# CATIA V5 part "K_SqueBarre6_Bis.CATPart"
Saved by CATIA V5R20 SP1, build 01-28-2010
Part number: squelette_barre_6_bis
Publications: "Point.1", "Point.2", "Droite.1", "Point.3", "Plan.1", "Droite.2", "Droite.3", "Droite.4", "Point.4"
Bounding box of the stored display mesh (mm): x 0 to 0, y -2 to 20, z 0 to 45
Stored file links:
  G:\Khaled_CFAO_2011\ST2M\ST2M_GR2\gcausse\Khaled\CAD_ThinkMotion\K_SqueBarre6_Bis.CATPart
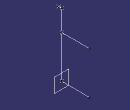
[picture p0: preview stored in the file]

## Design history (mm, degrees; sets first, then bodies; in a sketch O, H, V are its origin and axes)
Set1
  Point1: (0, 0, 0)
  Point2: (0, 0, 30)
  Line1: type PtPt, FirstPoint Point2, SecondPoint Point1, Start 15
  Point3: (0, 0, 45)
  Plane1: type Offset, RefPlane zx-plane, Offset 0
  Line2: type PtDir, RefPoint Point1, Direction Plane1, Start 0, End 20
  Line3: type PtDir, RefPoint Point2, Direction Plane1, Start 0, End 20
  Line4: type PtDir, RefPoint Point3, Direction Plane1, Start 0, End 2
  Point4: (0, -2, 45)
Body1 (main body)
